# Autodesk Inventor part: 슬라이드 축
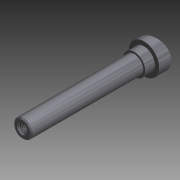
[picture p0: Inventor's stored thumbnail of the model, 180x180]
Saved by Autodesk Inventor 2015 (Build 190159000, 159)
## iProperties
Created: 2012-05
Part Number: 슬라이드 축
Document SubType Name: 모델링
Designer: SeoGD™
Mass: 169.348 g
Surface Area: 67.586 cm^2
Volume: 21.5729 cm^3
Density: 7.85 g/cm^3
Material: 강철
Appearance: 플레이트
변환 표준: STEP AP214IS
파일 이름: C:\Users\SeoGD\Desktop\?쒗뿕\異?stp
전처리기: Build: 253, Release: 2010 SP1 - Date: Wed 07/29/2009
전송 단위: 밀리미터
불확실성: 0.01
Author: SeoGD™
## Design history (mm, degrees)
sketch "스케치1"
  geometry: L1 (0, 100)-(7.5, 100); L2 (7.5, 100)-(7.5, 0); L3 (7.5, 0)-(12.5, 0); L4 (12.5, 0)-(12.5, -17); L5 (12.5, -17)-(0, -17); L6 (0, -17)-(0, 100); 1 further point
  constraints: 12 end point, 2 parallel, 2 point on line, 1 perpendicular, 1 vertical
  dimensions: "d0" = 100 distance from line of L1 point (0, 0); "d1" = 15 diameter of L2 L6; "d2" = 25 diameter of L4 L6; "d3" = 17 distance of L3.end L4.end
revolve "회전1" sketch "스케치1" stored, may be unused: angle "d4" = 90 deg
sketch "스케치2"
  geometry: L1 (12.5, 0)-(12.5, -17) reference; L2 (-12.5, -17)-(12.5, -17) reference; L3 (-12.5, 0)-(-12.5, -17) reference; L4 (12.5, -5)-(-12.5, -11.699); L5 (-12.5, 0)-(12.5, 0) reference; 1 further point
  constraints: 2 end point, 2 point on line
  dimensions: "d5" = 75 deg angle of L1 L4; "d6" = 5 distance from line of L4.start L5
extrude "돌출1" cut sketch "스케치2" stored distance "d7" = 10; taper "d8" = 0 deg
chamfer "모따기1" distance "d9" = 1; stored, may be unused: second distance "d10" = 2, angle "d11" = 45 deg
fillet "모깎기1" dims "d12" = 0.5
hole "구멍1" diameter "d15" = 6.647; stored, may be unused: countersink angle "d19" = 90 deg, drill point angle "d21" = 118 deg; dims "d13" = 10, "d14" = 10, "d16" = 17, "d17" = 4, "d18" = 2, "d20" = 20
chamfer "모따기2" distance "d22" = 1; stored, may be unused: second distance "d23" = 2, angle "d24" = 45 deg
sketch "스케치3"
  geometry: C1 r 9 at (0, 0); 1 further point
  constraints: 1 centre point, 1 coincident
  dimensions: "d25" = 18 diameter of C1
extrude "돌출2" join sketch "스케치3" distance "d26" = 8; taper "d27" = 0 deg
node "솔리드1"
node "솔리드 본체"
node "곡면 본체"
node "솔리드2"
